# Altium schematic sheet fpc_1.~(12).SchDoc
size A; SheetNumber: 1; SheetTotal: 2
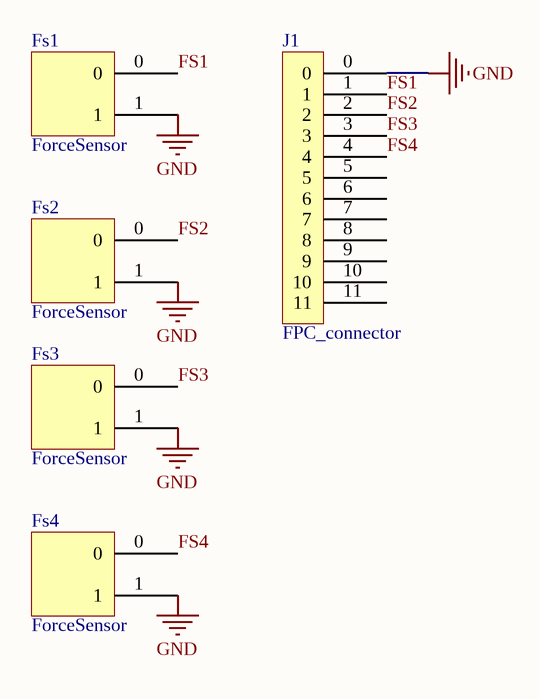
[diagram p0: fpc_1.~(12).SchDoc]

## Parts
Fs1  ForceSensor  [sensor_connector]
Fs2  ForceSensor  [sensor_connector]
Fs3  ForceSensor  [sensor_connector]
Fs4  ForceSensor  [sensor_connector]
J1  FPC_connector  [FPC_connector]

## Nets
GND: Fs1.1 Fs2.1 Fs3.1 Fs4.1 J1.0
FS1: Fs1.0 J1.1
FS2: Fs2.0 J1.2
FS3: Fs3.0 J1.3
FS4: Fs4.0 J1.4

Not connected (* = marked no-connect by the designer): J1 5 6 7 8 9 10 11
